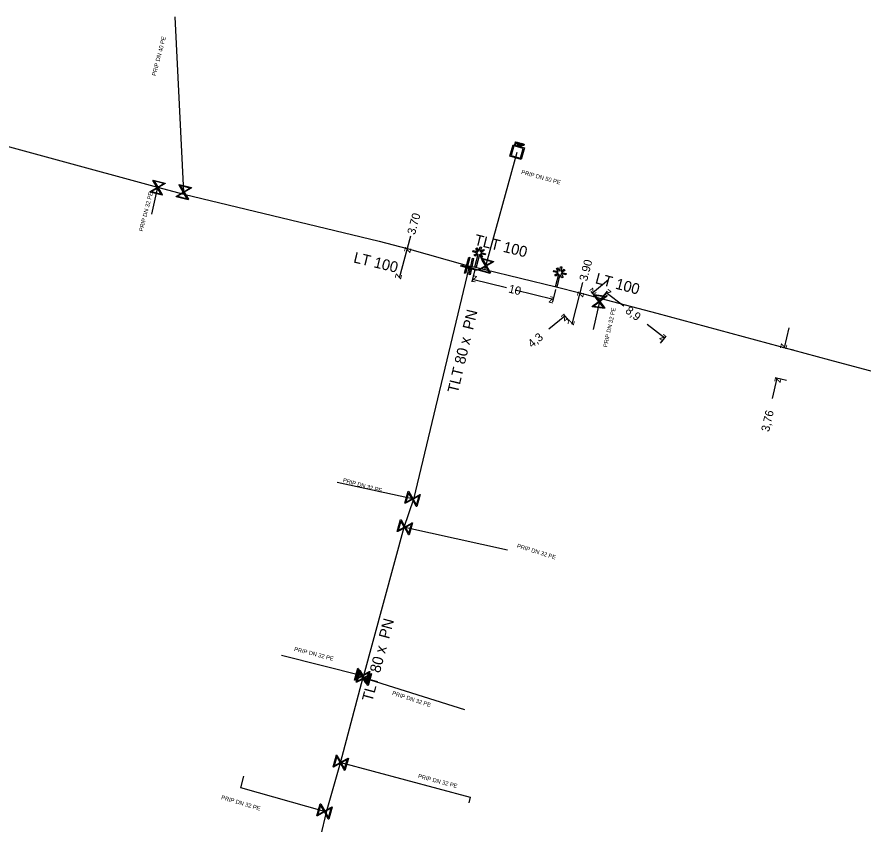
# Model space of a CAD drawing. Extents: x -643544 to -637295, y -1119190 to -1111715.
# Drawn here: x -642023 to -641921.1, y -1114994.1 to -1114896.9 of the extents above; entities that cross this region are included whole.
import ezdxf

# ---------------------------------------------------------------- set-up
doc = ezdxf.new("R2010")
doc.units = 0
for name, color, linetype in [('Default', 7, 'Continuous'), ('VP Kótování', 7, 'Continuous'), ('VP Popis přípojky', 7, 'Continuous'), ('VP Přípojka', 7, 'Continuous'), ('VP Změna materiálu', 7, 'Continuous'), ('VP Řad', 7, 'Continuous'), ('VP Řad - popis', 7, 'Continuous'), ('VP Šachta', 7, 'Continuous'), ('VP Šoupě', 7, 'Continuous')]:
    doc.layers.add(name, color=color, linetype=linetype)

msp = doc.modelspace()

# ---------------------------------------------------------------- linework, layer by layer
at = {"layer": 'Default'}
for points in [[(-641962.78, -1114911.98), (-641962.75, -1114911.99), (-641962.73, -1114912), (-641962.71, -1114912.01), (-641962.69, -1114912.03), (-641962.68, -1114912.04), (-641962.68, -1114912.07), (-641962.67, -1114912.09), (-641962.68, -1114912.12), (-641962.69, -1114912.16), (-641962.73, -1114912.18), (-641962.76, -1114912.21), (-641962.84, -1114912.19)], [(-641962.83, -1114912.15), (-641962.78, -1114912.16), (-641962.76, -1114912.15), (-641962.74, -1114912.14), (-641962.73, -1114912.11), (-641962.72, -1114912.08), (-641962.73, -1114912.07), (-641962.73, -1114912.05), (-641962.75, -1114912.04), (-641962.76, -1114912.03), (-641962.79, -1114912.02)], [(-641962.48, -1114912.36), (-641962.49, -1114912.32), (-641962.5, -1114912.3), (-641962.51, -1114912.28), (-641962.52, -1114912.27), (-641962.53, -1114912.26), (-641962.54, -1114912.26), (-641962.54, -1114912.25), (-641962.56, -1114912.25)], [(-641962.5, -1114912.22), (-641962.47, -1114912.23), (-641962.45, -1114912.23), (-641962.43, -1114912.23), (-641962.42, -1114912.22), (-641962.41, -1114912.2), (-641962.4, -1114912.19), (-641962.4, -1114912.16), (-641962.41, -1114912.14), (-641962.42, -1114912.12), (-641962.46, -1114912.11)], [(-641962.45, -1114912.07), (-641962.41, -1114912.08), (-641962.39, -1114912.1), (-641962.36, -1114912.12), (-641962.36, -1114912.14), (-641962.35, -1114912.17), (-641962.36, -1114912.2), (-641962.37, -1114912.24), (-641962.4, -1114912.26), (-641962.43, -1114912.27), (-641962.48, -1114912.27), (-641962.46, -1114912.28), (-641962.46, -1114912.29), (-641962.44, -1114912.32), (-641962.43, -1114912.35)], [(-641962.01, -1114912.19), (-641961.98, -1114912.2), (-641961.96, -1114912.21), (-641961.94, -1114912.22), (-641961.92, -1114912.24), (-641961.91, -1114912.26), (-641961.9, -1114912.28), (-641961.9, -1114912.31), (-641961.91, -1114912.33), (-641961.92, -1114912.38), (-641961.95, -1114912.4), (-641961.99, -1114912.42), (-641962.06, -1114912.4)], [(-641962.05, -1114912.36), (-641962.01, -1114912.37), (-641961.99, -1114912.36), (-641961.96, -1114912.35), (-641961.95, -1114912.32), (-641961.95, -1114912.3), (-641961.95, -1114912.28), (-641961.96, -1114912.26), (-641961.98, -1114912.25), (-641961.99, -1114912.25), (-641962.02, -1114912.24)]]:
    msp.add_open_spline(points, degree=3, dxfattribs=at)
at = {"layer": 'VP Kótování'}
for points in [[(-641975.58, -1114923.31), (-641975.98, -1114924.78)], [(-641975.98, -1114924.78), (-641976.96, -1114928.35)], [(-641967.81, -1114927.33), (-641968.17, -1114928.8)], [(-641964.01, -1114929.52), (-641968.1, -1114928.51)], [(-641951.73, -1114928.58), (-641953.66, -1114930.17)], [(-641962.95, -1114929.78), (-641958.39, -1114930.91)], [(-641958.1, -1114929.72), (-641958.46, -1114931.2)], [(-641954.85, -1114928.91), (-641955.17, -1114930.13)], [(-641955.17, -1114930.13), (-641956.15, -1114933.91)], [(-641953.15, -1114930.79), (-641953.82, -1114929.98)], [(-641952.52, -1114930.78), (-641951.86, -1114929.92)], [(-641949.89, -1114931.75), (-641952.01, -1114930.12)], [(-641956.47, -1114933.52), (-641957.14, -1114932.71)], [(-641958.91, -1114934.49), (-641956.98, -1114932.9)], [(-641947.08, -1114933.9), (-641944.95, -1114935.54)], [(-641930, -1114934.33), (-641930.56, -1114936.77)], [(-641945.47, -1114936.2), (-641944.8, -1114935.34)], [(-641929.45, -1114937.03), (-641930.8, -1114936.71)], [(-641931.96, -1114942.87), (-641931.4, -1114940.43)], [(-641930.3, -1114940.69), (-641931.65, -1114940.38)]]:
    msp.add_lwpolyline(points, dxfattribs=at)
at = {"layer": 'VP Přípojka'}
for points in [[(-642002.87, -1114918.26), (-642002.88, -1114918.02), (-642003.91, -1114896.92)], [(-641966.62, -1114927.32), (-641962.72, -1114913.19)], [(-642006.03, -1114917.4), (-642006.76, -1114920.65)], [(-641952.77, -1114930.77), (-641952.83, -1114931.18), (-641953.56, -1114934.57)], [(-641975.22, -1114954.99), (-641975.33, -1114954.95), (-641984.42, -1114952.99)], [(-641976.39, -1114958.41), (-641976.26, -1114958.36), (-641963.88, -1114961.06)], [(-641981.24, -1114976.27), (-641981.41, -1114976.26), (-641991.1, -1114973.8)], [(-641981.32, -1114976.47), (-641981.19, -1114976.5), (-641969.09, -1114980.3)], [(-641984.06, -1114986.75), (-641983.98, -1114986.7), (-641968.39, -1114990.88), (-641968.55, -1114991.54)], [(-641985.75, -1114992.67), (-641985.93, -1114992.58), (-641996, -1114989.74), (-641995.66, -1114988.32)]]:
    msp.add_lwpolyline(points, dxfattribs=at)
at = {"layer": 'VP Změna materiálu'}
for points in [[(-641967.33, -1114925.12), (-641967.19, -1114924.59), (-641967.04, -1114924.63), (-641967.17, -1114925.15), (-641966.77, -1114924.91), (-641966.69, -1114925.04), (-641967.09, -1114925.28), (-641966.53, -1114925.42), (-641966.57, -1114925.58), (-641967.14, -1114925.43), (-641966.9, -1114925.84), (-641967.03, -1114925.92), (-641967.27, -1114925.52), (-641967.66, -1114927.05), (-641967.81, -1114927.02), (-641967.42, -1114925.48), (-641967.82, -1114925.72), (-641967.9, -1114925.58), (-641967.5, -1114925.34), (-641968.06, -1114925.2), (-641968.03, -1114925.05), (-641967.47, -1114925.19), (-641967.7, -1114924.79), (-641967.57, -1114924.71), (-641967.33, -1114925.12)], [(-641957.63, -1114927.51), (-641957.5, -1114926.99), (-641957.35, -1114927.02), (-641957.48, -1114927.54), (-641957.08, -1114927.3), (-641957, -1114927.43), (-641957.4, -1114927.68), (-641956.84, -1114927.81), (-641956.87, -1114927.96), (-641957.44, -1114927.82), (-641957.2, -1114928.23), (-641957.33, -1114928.31), (-641957.57, -1114927.91), (-641957.95, -1114929.45), (-641958.1, -1114929.41), (-641957.72, -1114927.87), (-641958.12, -1114928.12), (-641958.2, -1114927.98), (-641957.8, -1114927.74), (-641958.37, -1114927.6), (-641958.33, -1114927.45), (-641957.77, -1114927.58), (-641958.01, -1114927.19), (-641957.88, -1114927.11), (-641957.63, -1114927.51)]]:
    msp.add_lwpolyline(points, dxfattribs=at)
at = {"layer": 'VP Řad'}
for points in [[(-642038.84, -1114908.59), (-642032.83, -1114910.17), (-642030.69, -1114910.72), (-642006.03, -1114917.4), (-642002.87, -1114918.26), (-641979.36, -1114923.91), (-641975.98, -1114924.78), (-641968.75, -1114926.83), (-641968.44, -1114926.91)], [(-641968.44, -1114926.91), (-641968.54, -1114927.13), (-641975.22, -1114954.99), (-641976.39, -1114958.41), (-641981.24, -1114976.27), (-641981.27, -1114976.38), (-641981.32, -1114976.47), (-641984.06, -1114986.75), (-641985.75, -1114992.67), (-641987.11, -1114998.43), (-641989.1, -1115005.65), (-641990.32, -1115010.82), (-641992.94, -1115020.25), (-641994.61, -1115026.34), (-641994.69, -1115026.66), (-641995.96, -1115030.87), (-642000.27, -1115047.2), (-642001.11, -1115050.36), (-642003.1, -1115057.72), (-642003.38, -1115058.49), (-642006.95, -1115072.6), (-642007.07, -1115072.95)], [(-641968.44, -1114926.91), (-641968.24, -1114926.96), (-641967.74, -1114927.03)], [(-641967.74, -1114927.03), (-641966.62, -1114927.32), (-641958.03, -1114929.43)], [(-641958.03, -1114929.43), (-641955.17, -1114930.13), (-641952.77, -1114930.77), (-641945.91, -1114932.59), (-641925.1, -1114938.22), (-641918.66, -1114939.94), (-641918.55, -1114939.97), (-641915.05, -1114940.68), (-641914.75, -1114941.22), (-641914.54, -1114941.25)]]:
    msp.add_lwpolyline(points, dxfattribs=at)
at = {"layer": 'VP Šachta'}
for points in [[(-641961.85, -1114912.68), (-641962.24, -1114914.08), (-641963.6, -1114913.7), (-641963.21, -1114912.3), (-641961.85, -1114912.68)], [(-641963.13, -1114912.45), (-641963.45, -1114913.61), (-641962.32, -1114913.92), (-641962, -1114912.76), (-641963.13, -1114912.45)], [(-641963.01, -1114912.29), (-641962.91, -1114911.94), (-641962.78, -1114911.98)], [(-641962.84, -1114912.19), (-641962.93, -1114912.16), (-641962.96, -1114912.3), (-641963.01, -1114912.29)], [(-641962.79, -1114912.02), (-641962.88, -1114912), (-641962.91, -1114912.12)], [(-641962.91, -1114912.12), (-641962.83, -1114912.15)], [(-641962.7, -1114912.38), (-641962.61, -1114912.03), (-641962.45, -1114912.07)], [(-641962.56, -1114912.25), (-641962.61, -1114912.23), (-641962.66, -1114912.39), (-641962.7, -1114912.38)], [(-641962.46, -1114912.11), (-641962.57, -1114912.08), (-641962.6, -1114912.2)], [(-641962.6, -1114912.2), (-641962.5, -1114912.22)], [(-641962.43, -1114912.35), (-641962.4, -1114912.46), (-641962.46, -1114912.44), (-641962.48, -1114912.36)], [(-641962.35, -1114912.47), (-641962.26, -1114912.13), (-641962.21, -1114912.14), (-641962.31, -1114912.49), (-641962.35, -1114912.47)], [(-641962.24, -1114912.5), (-641962.14, -1114912.16), (-641962.01, -1114912.19)], [(-641962.06, -1114912.4), (-641962.15, -1114912.38), (-641962.19, -1114912.52), (-641962.24, -1114912.5)], [(-641962.02, -1114912.24), (-641962.11, -1114912.21), (-641962.14, -1114912.34)], [(-641962.14, -1114912.34), (-641962.05, -1114912.36)]]:
    msp.add_lwpolyline(points, dxfattribs=at)
at = {"layer": 'VP Šoupě'}
for points in [[(-642006.58, -1114916.55), (-642005.13, -1114916.92), (-642005.14, -1114916.98), (-642005.26, -1114917.04), (-642005.98, -1114917.47), (-642005.48, -1114918.31), (-642005.5, -1114918.37), (-642006.95, -1114918), (-642006.94, -1114917.93), (-642006.1, -1114917.44), (-642006.53, -1114916.72), (-642006.6, -1114916.61), (-642006.58, -1114916.55)], [(-642005.62, -1114918.24), (-642006.05, -1114917.52), (-642006.78, -1114917.95), (-642005.62, -1114918.24)], [(-642006.45, -1114916.67), (-642006.02, -1114917.4), (-642005.3, -1114916.97), (-642006.45, -1114916.67)], [(-642002.34, -1114918.93), (-642003.79, -1114918.56), (-642003.78, -1114918.5), (-642003.66, -1114918.44), (-642002.94, -1114918), (-642003.44, -1114917.17), (-642003.43, -1114917.11), (-642001.97, -1114917.47), (-642001.99, -1114917.54), (-642002.82, -1114918.03), (-642002.39, -1114918.75), (-642002.32, -1114918.86), (-642002.34, -1114918.93)], [(-642003.3, -1114917.23), (-642002.87, -1114917.96), (-642002.15, -1114917.52), (-642003.3, -1114917.23)], [(-642002.47, -1114918.8), (-642002.9, -1114918.08), (-642003.62, -1114918.51), (-642002.47, -1114918.8)], [(-641968.41, -1114925.88), (-641968.96, -1114927.81), (-641969.08, -1114927.77), (-641968.54, -1114925.85), (-641968.41, -1114925.88)], [(-641967.97, -1114925.99), (-641968.39, -1114927.95), (-641968.51, -1114927.92), (-641968.09, -1114925.96), (-641967.97, -1114925.99)], [(-641967.02, -1114925.96), (-641965.58, -1114926.36), (-641965.59, -1114926.42), (-641965.71, -1114926.48), (-641966.44, -1114926.9), (-641965.96, -1114927.74), (-641965.97, -1114927.81), (-641967.42, -1114927.41), (-641967.4, -1114927.34), (-641966.56, -1114926.87), (-641966.97, -1114926.14), (-641967.04, -1114926.03), (-641967.02, -1114925.96)], [(-641966.89, -1114926.09), (-641966.48, -1114926.82), (-641965.75, -1114926.41), (-641966.89, -1114926.09)], [(-641967.59, -1114927.44), (-641969.52, -1114926.94), (-641969.49, -1114926.82), (-641967.56, -1114927.32), (-641967.59, -1114927.44)], [(-641966.1, -1114927.68), (-641966.51, -1114926.94), (-641967.24, -1114927.36), (-641966.1, -1114927.68)], [(-641952.19, -1114932.03), (-641953.68, -1114931.82), (-641953.67, -1114931.75), (-641953.56, -1114931.68), (-641952.89, -1114931.17), (-641953.48, -1114930.4), (-641953.47, -1114930.33), (-641951.98, -1114930.54), (-641951.99, -1114930.61), (-641952.77, -1114931.19), (-641952.26, -1114931.86), (-641952.18, -1114931.96), (-641952.19, -1114932.03)], [(-641953.33, -1114930.45), (-641952.82, -1114931.12), (-641952.15, -1114930.61), (-641953.33, -1114930.45)], [(-641952.33, -1114931.91), (-641952.84, -1114931.24), (-641953.51, -1114931.75), (-641952.33, -1114931.91)], [(-641974.4, -1114954.43), (-641974.81, -1114955.88), (-641974.88, -1114955.86), (-641974.94, -1114955.74), (-641975.35, -1114955.01), (-641976.19, -1114955.48), (-641976.26, -1114955.47), (-641975.85, -1114954.02), (-641975.78, -1114954.04), (-641975.31, -1114954.89), (-641974.58, -1114954.48), (-641974.47, -1114954.42), (-641974.4, -1114954.43)], [(-641976.12, -1114955.35), (-641975.39, -1114954.93), (-641975.8, -1114954.2), (-641976.12, -1114955.35)], [(-641974.54, -1114954.56), (-641975.27, -1114954.97), (-641974.86, -1114955.7), (-641974.54, -1114954.56)], [(-641975.33, -1114957.84), (-641975.74, -1114959.29), (-641975.81, -1114959.27), (-641975.86, -1114959.15), (-641976.27, -1114958.42), (-641977.12, -1114958.89), (-641977.19, -1114958.88), (-641976.78, -1114957.43), (-641976.71, -1114957.45), (-641976.24, -1114958.3), (-641975.51, -1114957.89), (-641975.4, -1114957.82), (-641975.33, -1114957.84)], [(-641977.05, -1114958.76), (-641976.32, -1114958.34), (-641976.73, -1114957.61), (-641977.05, -1114958.76)], [(-641975.47, -1114957.97), (-641976.2, -1114958.38), (-641975.79, -1114959.11), (-641975.47, -1114957.97)], [(-641980.48, -1114975.74), (-641980.89, -1114977.19), (-641980.96, -1114977.17), (-641981.01, -1114977.05), (-641981.42, -1114976.32), (-641982.27, -1114976.79), (-641982.34, -1114976.78), (-641981.93, -1114975.33), (-641981.86, -1114975.35), (-641981.39, -1114976.2), (-641980.66, -1114975.79), (-641980.55, -1114975.72), (-641980.48, -1114975.74)], [(-641982.2, -1114976.66), (-641981.47, -1114976.24), (-641981.88, -1114975.51), (-641982.2, -1114976.66)], [(-641980.26, -1114975.99), (-641980.68, -1114977.43), (-641980.74, -1114977.41), (-641980.8, -1114977.29), (-641981.21, -1114976.56), (-641982.05, -1114977.03), (-641982.12, -1114977.01), (-641981.7, -1114975.57), (-641981.64, -1114975.59), (-641981.17, -1114976.44), (-641980.44, -1114976.03), (-641980.32, -1114975.97), (-641980.26, -1114975.99)], [(-641981.98, -1114976.89), (-641981.25, -1114976.48), (-641981.66, -1114975.75), (-641981.98, -1114976.89)], [(-641980.62, -1114975.87), (-641981.35, -1114976.28), (-641980.94, -1114977.01), (-641980.62, -1114975.87)], [(-641980.4, -1114976.11), (-641981.13, -1114976.52), (-641980.72, -1114977.25), (-641980.4, -1114976.11)], [(-641983.05, -1114986.19), (-641983.47, -1114987.63), (-641983.53, -1114987.61), (-641983.59, -1114987.49), (-641984, -1114986.76), (-641984.84, -1114987.23), (-641984.91, -1114987.21), (-641984.49, -1114985.77), (-641984.43, -1114985.79), (-641983.96, -1114986.64), (-641983.23, -1114986.23), (-641983.11, -1114986.17), (-641983.05, -1114986.19)], [(-641984.77, -1114987.09), (-641984.04, -1114986.68), (-641984.45, -1114985.95), (-641984.77, -1114987.09)], [(-641983.19, -1114986.31), (-641983.92, -1114986.72), (-641983.51, -1114987.45), (-641983.19, -1114986.31)], [(-641985, -1114992.06), (-641985.41, -1114993.51), (-641985.48, -1114993.49), (-641985.53, -1114993.37), (-641985.94, -1114992.64), (-641986.79, -1114993.11), (-641986.86, -1114993.1), (-641986.45, -1114991.65), (-641986.38, -1114991.67), (-641985.91, -1114992.52), (-641985.18, -1114992.11), (-641985.07, -1114992.04), (-641985, -1114992.06)], [(-641986.72, -1114992.98), (-641985.99, -1114992.56), (-641986.4, -1114991.83), (-641986.72, -1114992.98)], [(-641985.14, -1114992.19), (-641985.87, -1114992.6), (-641985.46, -1114993.33), (-641985.14, -1114992.19)]]:
    msp.add_lwpolyline(points, dxfattribs=at)

# ---------------------------------------------------------------- texts
at = {"layer": 'VP Kótování'}
for s, rotation, p in [('3.70', 74.7245, (-641975.04, -1114923.2)), ('z', 74.7245, (-641975.63, -1114925.39)), ('3.90', 75.465, (-641954.31, -1114928.8)), ('z', 254.7245, (-641977.31, -1114927.74)), ('z', 166.1319, (-641967.5, -1114928.15)), ('10', 346.1319, (-641963.84, -1114930.08)), ('z', 219.4277, (-641953.59, -1114929.47)), ('z', 142.4759, (-641951.31, -1114930.02)), ('z', 346.1319, (-641959, -1114931.27)), ('z', 75.465, (-641954.81, -1114930.74)), ('8,9', 322.4759, (-641949.79, -1114932.45)), ('z', 39.4277, (-641957.05, -1114933.61)), ('z', 255.465, (-641956.51, -1114933.3)), ('4,3', 39.4277, (-641960.94, -1114936.81)), ('z', 322.4759, (-641945.66, -1114935.63)), ('z', 257.0343, (-641930.93, -1114936.17)), ('z', 77.0343, (-641931.03, -1114941.03)), ('3,76', 77.0343, (-641932.39, -1114946.93))]:
    msp.add_text(s, height=1, rotation=rotation, dxfattribs=at).set_placement(p)
at = {"layer": 'VP Popis přípojky'}
for s, rotation, p in [('PRIP DN 40 PE', 75.377, (-642006.26, -1114904.06)), ('PRIP DN 50 PE', 344.5961, (-641962.28, -1114915.81)), ('PRIP DN 32 PE', 75.6064, (-642007.81, -1114922.78)), ('PRIP DN 32 PE', 77.8192, (-641951.88, -1114936.73)), ('PRIP DN 32 PE', 344.6937, (-641983.77, -1114952.91)), ('PRIP DN 32 PE', 342.7152, (-641962.8, -1114960.8)), ('PRIP DN 32 PE', 345.7622, (-641989.63, -1114973.25)), ('PRIP DN 32 PE', 342.1789, (-641977.84, -1114978.54)), ('PRIP DN 32 PE', 345.2465, (-641974.71, -1114988.54)), ('PRIP DN 32 PE', 343.4951, (-641998.42, -1114991.1))]:
    msp.add_text(s, height=0.5, rotation=rotation, dxfattribs=at).set_placement(p)
at = {"layer": 'VP Řad - popis'}
for s, rotation, p in [('TLT 100', 346.1947, (-641967.98, -1114924.33)), ('LT 100', 346.4723, (-641982.52, -1114926.46)), ('LT 100', 344.9185, (-641953.41, -1114928.96)), ('TLT 80 x  PN ', 76.5167, (-641969.88, -1114942.29)), ('TLT 80 x  PN ', 75.0185, (-641980.19, -1114979.44))]:
    msp.add_text(s, height=1.3, rotation=rotation, dxfattribs=at).set_placement(p)

doc.saveas('drawing.dxf')
